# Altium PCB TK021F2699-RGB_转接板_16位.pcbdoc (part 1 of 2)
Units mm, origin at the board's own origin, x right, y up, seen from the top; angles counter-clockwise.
Board outline 79.4 x 75.01 mm, 2 copper layers (Top Layer, Bottom Layer), stack 1.58 mm thick; 9 components, 29 nets, 98 pads, 116 vias.
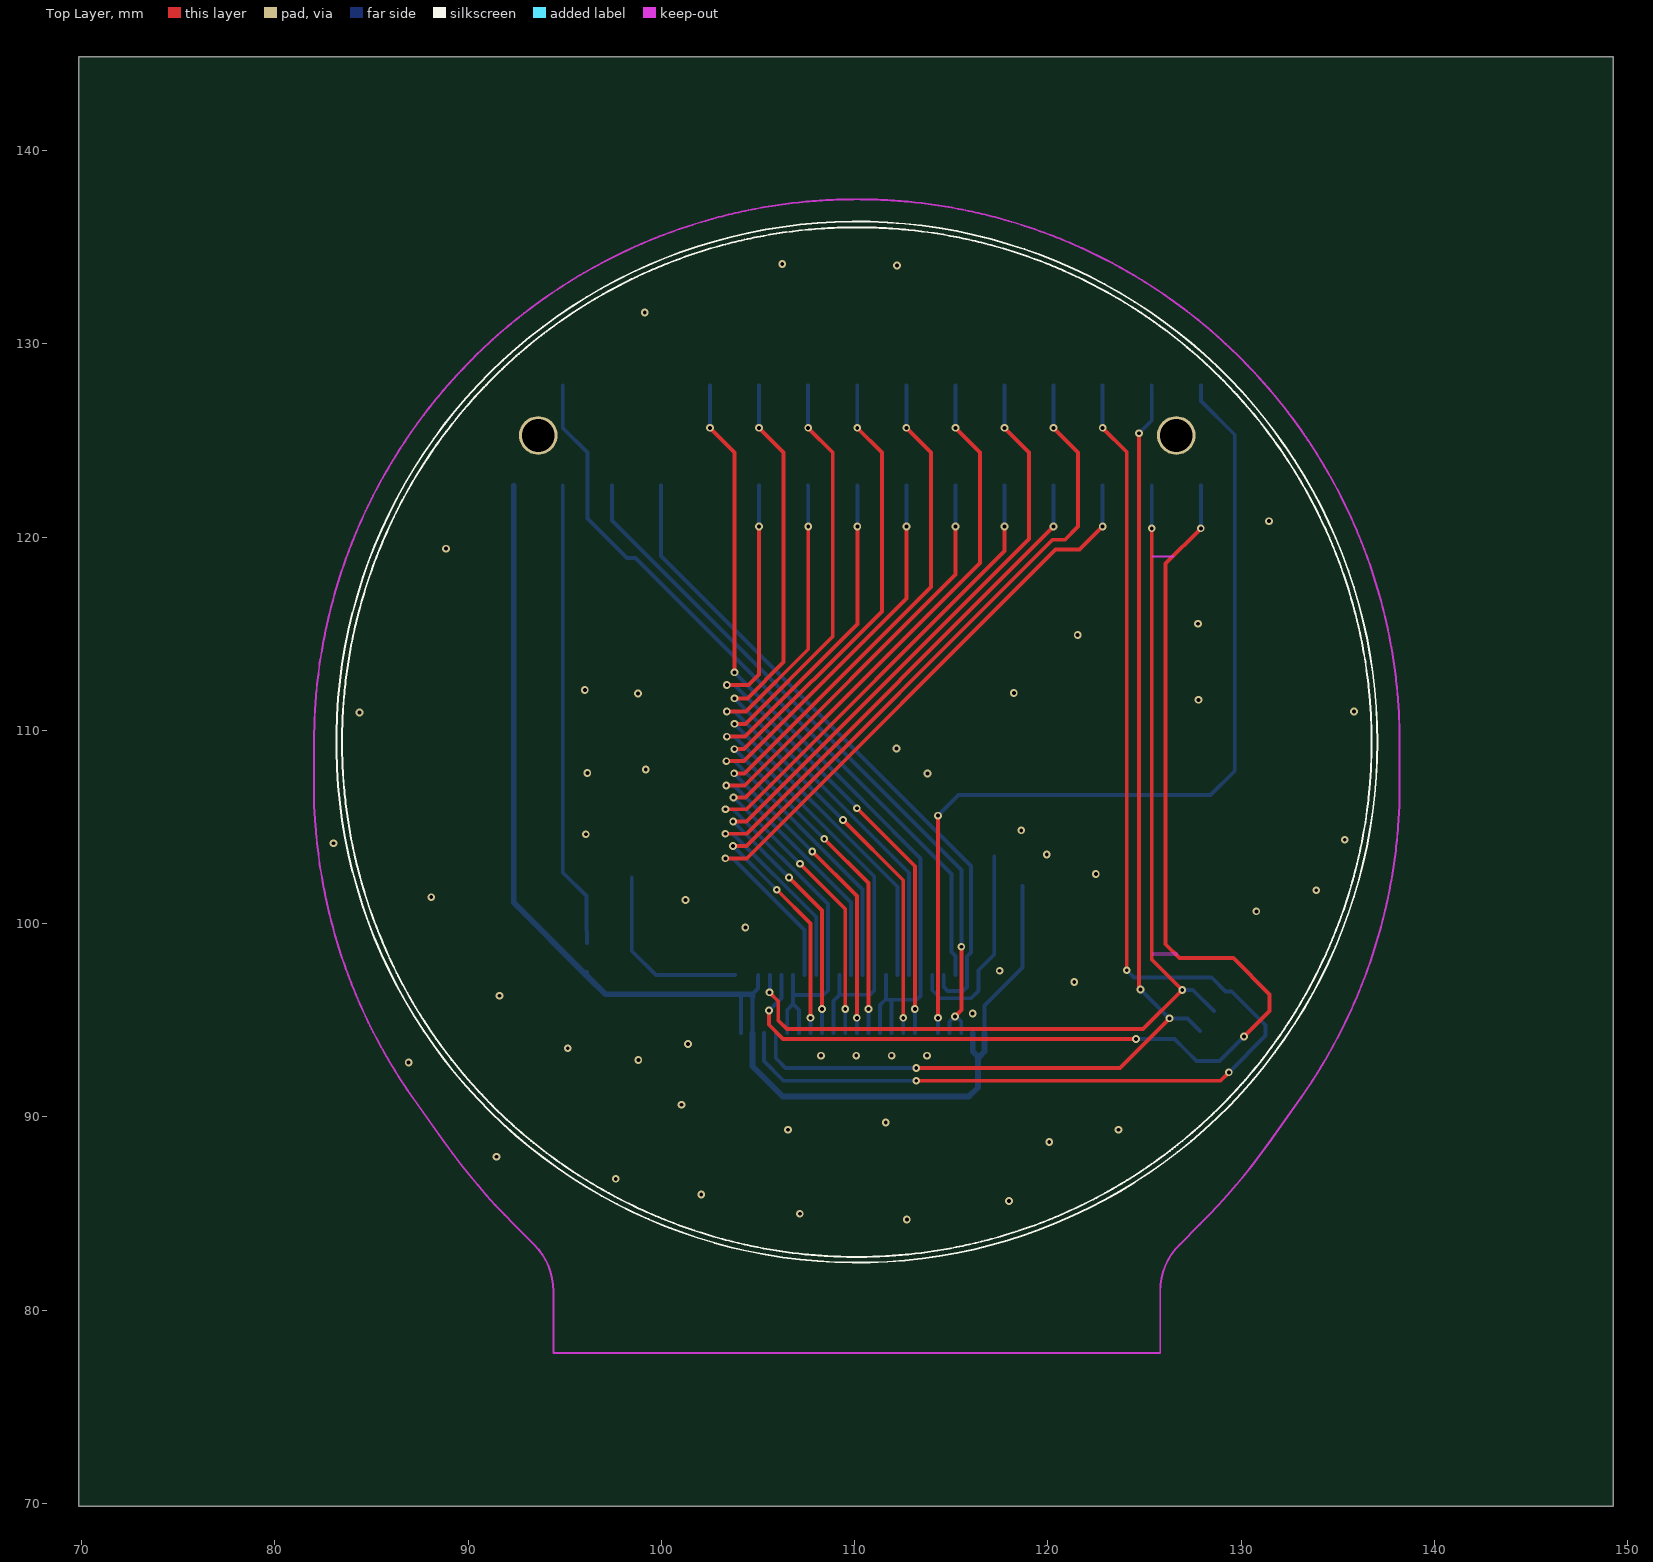
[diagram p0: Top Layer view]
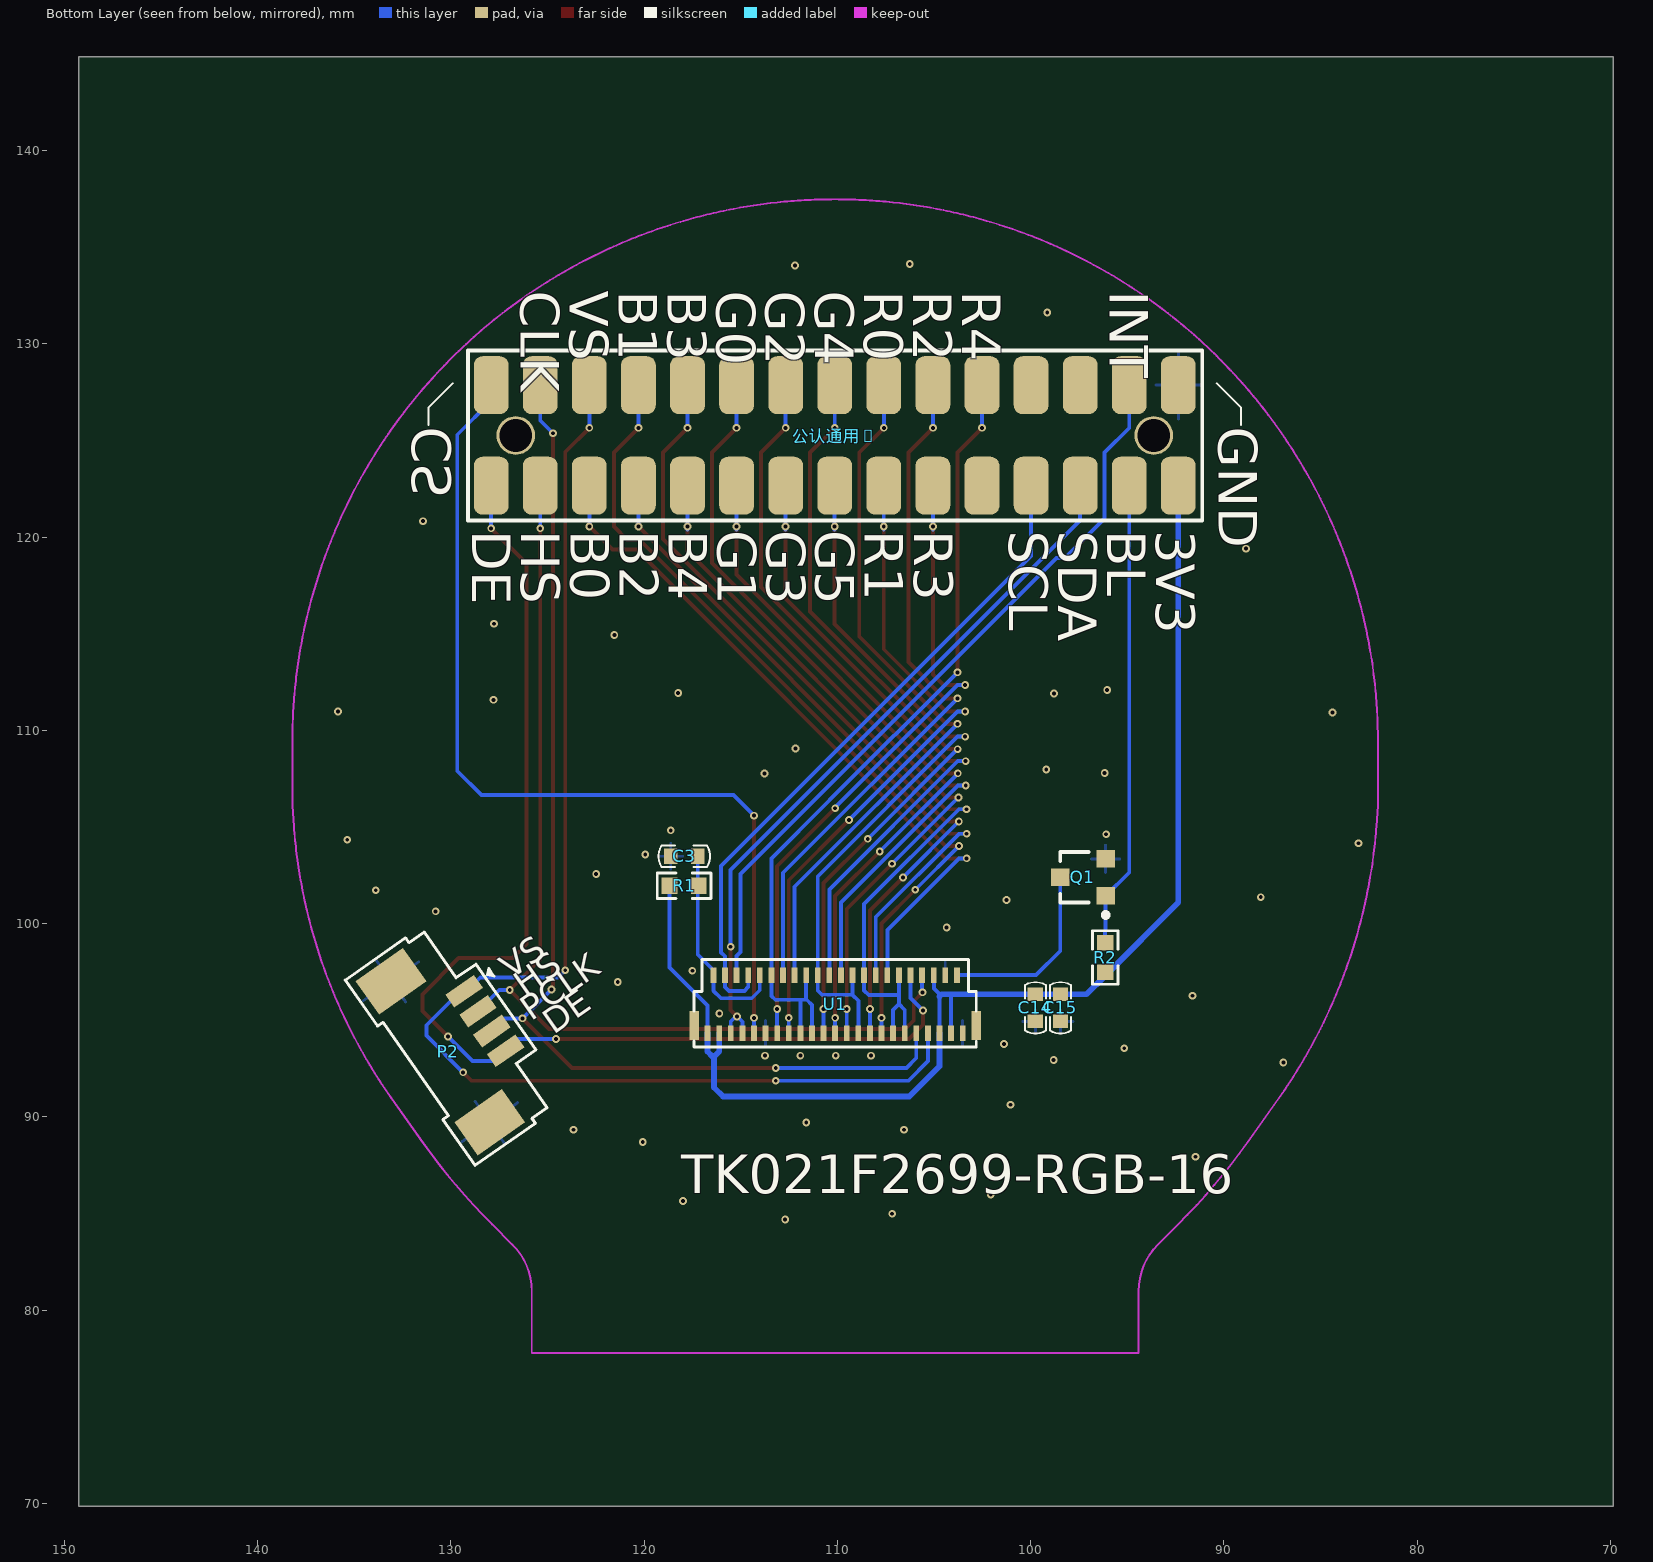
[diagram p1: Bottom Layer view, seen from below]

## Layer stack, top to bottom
Top Solder Mask Layer: solder mask 0.01, Dk 3.3
Top Layer: signal copper 0.035
Dielectric1: surface 1.51, FR4, Dk 4.5
Bottom Layer: signal copper 0.035
Bottom Solder Mask Layer: solder mask 0.01, Dk 3.3

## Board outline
149.25,69.85 69.85,69.85 69.85,144.856 149.25,144.856

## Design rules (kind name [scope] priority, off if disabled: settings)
BoardOutlineClearance Clearance [All] p0: genericclearance=0.254 ignorepadtopadclearanceinfootprint=FALSE except(0: Arc-SplitContinuation Track-SplitContinuation SMDPad-SplitContinuation THPad-SplitContinuation Via-SplitContinuation Fill-SplitContinuation Poly-SplitContinuation Region-SplitContinuation Text-SplitContinuation)
BoardOutlineClearance Clearance_Polygon [All] p0: genericclearance=0.254 ignorepadtopadclearanceinfootprint=FALSE except(0: Arc-SplitContinuation Track-SplitContinuation SMDPad-SplitContinuation THPad-SplitContinuation Via-SplitContinuation Fill-SplitContinuation Poly-SplitContinuation Region-SplitContinuation Text-SplitContinuation)
BoardOutlineClearance Plane_PlaneConnect [All] p0: genericclearance=0.254 ignorepadtopadclearanceinfootprint=FALSE except(0: Arc-SplitContinuation Track-SplitContinuation SMDPad-SplitContinuation THPad-SplitContinuation Via-SplitContinuation Fill-SplitContinuation Poly-SplitContinuation Region-SplitContinuation Text-SplitContinuation)
BoardOutlineClearance Copper_PolygonConnect [All] p0: genericclearance=0.254 ignorepadtopadclearanceinfootprint=FALSE except(0: Arc-SplitContinuation Track-SplitContinuation SMDPad-SplitContinuation THPad-SplitContinuation Via-SplitContinuation Fill-SplitContinuation Poly-SplitContinuation Region-SplitContinuation Text-SplitContinuation)
BoardOutlineClearance Copper_PolygonConnect_1 [All] p0: genericclearance=0.254 ignorepadtopadclearanceinfootprint=FALSE except(0: Arc-SplitContinuation Track-SplitContinuation SMDPad-SplitContinuation THPad-SplitContinuation Via-SplitContinuation Fill-SplitContinuation Poly-SplitContinuation Region-SplitContinuation Text-SplitContinuation)
BoardOutlineClearance otherClearance [All] p0: genericclearance=0.254 ignorepadtopadclearanceinfootprint=FALSE except(0: Arc-SplitContinuation Track-SplitContinuation SMDPad-SplitContinuation THPad-SplitContinuation Via-SplitContinuation Fill-SplitContinuation Poly-SplitContinuation Region-SplitContinuation Text-SplitContinuation)
Clearance [All] p1: gap=0.178 ignorepadtopadclearanceinfootprint=FALSE
Clearance Clearance_Polygon [All] p1: gap=0.178 ignorepadtopadclearanceinfootprint=FALSE
Clearance Plane_PlaneConnect [All] p1: gap=0.178 ignorepadtopadclearanceinfootprint=FALSE
Clearance Copper_PolygonConnect [All] p1: gap=0.178 ignorepadtopadclearanceinfootprint=FALSE
Clearance Copper_PolygonConnect_1 [All] p1: gap=0.178 ignorepadtopadclearanceinfootprint=FALSE
Clearance otherClearance [All] p1: gap=0.178 ignorepadtopadclearanceinfootprint=FALSE
DiffPairsRouting [All] p1: maxuncoupledlength=500 minlimit=5.9055 maxlimit=Infinity mostfreqgap=7.874 toplayer_minwidth=7.874 toplayer_prefwidth=7.874 toplayer_maxwidth=7.874 bottomlayer_minwidth=7.874 bottomlayer_prefwidth=7.874 bottomlayer_maxwidth=7.874
PolygonConnect [All] p1: connectstyle=Relief reliefentries=4 reliefconductorwidth=5.9055 polygonreliefangle="90 Angle" airgapwidth=10
PolygonConnect PolygonConnect_1 [All] p1: connectstyle=Direct reliefentries=4 reliefconductorwidth=10 polygonreliefangle="90 Angle" airgapwidth=10
RoutingVias [All] p1: viastyle="Through Hole" holewidth=7.874 minholewidth=7.874 maxholewidth=27.9922 width=7.874 minwidth=7.874 maxwidth=27.9922
SolderMaskExpansion [All] p1: useseparateexpansions=TRUE expansion=3.937 expansionbottom=3.937
Width [All] p1: maxlimit=16 minlimit=8 preferedwidth=8
2 further rules are at their usual default settings.

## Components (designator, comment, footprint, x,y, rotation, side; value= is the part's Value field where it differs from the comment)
C3 "" C0603 117.932,103.48 r0 bottom
C14 "" C0603-1 99.746,96.345 r270 bottom
C15 "" C0603-2 98.45,96.345 r270 bottom
P2 "" BHEADSMD1x4 129.311,96.495 r55 bottom locked
Q1 "" SOT23A 96.114,101.448 r90 bottom
R1 "" R0603 117.932,101.956 r0 bottom
R2 "" R0603 96.139,98.247 r270 bottom
U1 "" TK-45P 103.512,94.336 r0 bottom locked
公认通用1 "" P_Head_2x15 127.912,127.864 r180 bottom locked

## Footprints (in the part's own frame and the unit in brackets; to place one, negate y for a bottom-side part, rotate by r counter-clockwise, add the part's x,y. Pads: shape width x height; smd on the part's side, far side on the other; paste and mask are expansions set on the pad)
BHEADSMD1x4 [mil]
  rect 32x71 smd: 1(0,0) 2(-49.21,0) 3(-98.43,0) 4(-147.64,0)
  rect 83x118 smd: 5(102.36,110.24) 6(-248.03,110.24)
  silkscreen extent -303,-68 158,185
C0603 [mm]
  rect 0.7x0.8 smd: 1(-0.712,-0.007) 2(0.688,-0.007)
  silkscreen extent -1.33,-0.56 1.31,0.54
C0603-1 [mm]
  rect 0.7x0.8 smd: 1(0,0) 2(1.4,0)
  silkscreen extent -0.62,-0.55 2.02,0.55
C0603-2 [mm]
  rect 0.7x0.8 smd: 1(0,0) 2(1.4,0)
  silkscreen extent -0.62,-0.55 2.02,0.55
P_Head_2x15 [mm]
  round 2 hole 1.7: 0(1.27,-2.6) 0(34.29,-2.6)
  rrect50% 1.8x3 smd: 1(0,0) 2(0,-5.2) 3(2.54,0) 4(2.54,-5.2) 5(5.08,0) 6(5.08,-5.2) 7(7.62,0) 8(7.62,-5.2) 9(10.16,0) 10(10.16,-5.2) 11(12.7,0) 12(12.7,-5.2) 13(15.24,0) 14(15.24,-5.2) 15(17.78,0) 16(17.78,-5.2) 17(20.32,0) 18(20.32,-5.2) 19(22.86,0) 20(22.86,-5.2) 21(25.4,0) 22(25.4,-5.2) 23(27.94,0) 24(27.94,-5.2) 25(30.48,0) 26(30.48,-5.2) 27(33.02,0) 28(33.02,-5.2) 29(35.56,0) 30(35.56,-5.2)
  silkscreen extent -1.2,-7 36.8,1.8
R0603 [mm]
  rect 0.806x0.864 smd: 1(-0.753,0) 2(0.753,0)
  silkscreen extent -1.39,-0.66 1.39,0.66
SOT23A [mm]
  rect 0.9x0.95 smd: 1(0,0) 2(1.9,0) 3(0.95,2.35)
  silkscreen extent -1.12,-0.12 2.25,2.35
TK-45P [mm]
  rect 0.5x1.5 smd: 0(-0.7,-0.4) 0(13.9,-0.4)
  rect 0.3x0.8 smd: 1(0,0) 2(0.3,-3) 3(0.6,0) 4(0.9,-3) 5(1.2,0) 6(1.5,-3) 7(1.8,0) 8(2.1,-3) 9(2.4,0) 10(2.7,-3) 11(3,0) 12(3.3,-3) 13(3.6,0) 14(3.9,-3) 15(4.2,0) 16(4.5,-3) 17(4.8,0) 18(5.1,-3) 19(5.4,0) 20(5.7,-3) 21(6,0) 22(6.3,-3) 23(6.6,0) 24(6.9,-3) 25(7.2,0) 26(7.5,-3) 27(7.8,0) 28(8.1,-3) 29(8.4,0) 30(8.7,-3) 31(9,0) 32(9.3,-3) 33(9.6,0) 34(9.9,-3) 35(10.2,0) 36(10.5,-3) 37(10.8,0) 38(11.1,-3) 39(11.4,0) 40(11.7,-3) 41(12,0) 42(12.3,-3) 43(12.6,0) 44(12.9,-3) 45(13.2,0)
  silkscreen extent -0.7,-3.8 13.9,0.73

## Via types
v1: diameter 0.4, hole 0.2, Top Layer to Bottom Layer, 116 vias

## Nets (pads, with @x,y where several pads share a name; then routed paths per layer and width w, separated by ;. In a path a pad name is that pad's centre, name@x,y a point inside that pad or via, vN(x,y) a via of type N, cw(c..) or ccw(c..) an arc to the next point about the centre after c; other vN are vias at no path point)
3.3V: C14.1 C15.1 R1.2 R2.2 U1.3 U1.5 U1.6 U1.43 U1.45 公认通用1.30 | length 68.2
  Bottom Layer w0.2: R2.2@96.139,97.307 R2.2@96.139,97.494 ; U1.3@104.112,94.336 104.112,96.33 104.127,96.345 ; U1.5@104.712,94.336 104.712,96.228 104.712,96.355 105.004,96.647 105.004,97.328 U1.6@105.012,97.336 ; U1.45@116.712,94.336 116.712,95.757 118.686,97.731 R1.2@118.686,101.956
  Bottom Layer w0.3: 公认通用1.30@92.352,122.664 92.352,101.095 96.139,97.307 97.101,96.345 C15.1@98.45,96.345 C14.1@99.746,96.345 104.127,96.345 104.595,96.345 104.712,96.228 ; U1.5@104.712,94.336 104.712,92.617 106.279,91.05 115.909,91.05 116.383,91.524 116.383,93.116 116.112,93.387 U1.43@116.112,94.336 ; 116.441,93.116 116.712,93.387 U1.45@116.712,94.336
B0: U1.14 公认通用1.6 | length 36.7
  Top Layer w0.2: v1(103.308,103.378) 104.417,103.378 120.393,119.355 121.64,119.355 v1(122.832,120.546)
  Bottom Layer w0.2: v1(103.308,103.378) 103.708,103.378 107.412,99.674 U1.14@107.412,97.336 ; v1(122.832,120.546) 公认通用1.6@122.832,122.664
B1: U1.15 公认通用1.7 | length 43.9
  Top Layer w0.2: v1(103.708,104.014) 104.395,104.014 120.244,119.863 120.879,119.863 121.564,120.548 121.564,124.384 v1(120.292,125.656) ; v1(105.969,101.754) 107.712,100.011 v1(107.712,95.123)
  Bottom Layer w0.2: v1(103.708,104.014) v1(105.969,101.754) ; U1.15@107.712,94.336 v1(107.712,95.123) ; v1(120.292,125.656) 公认通用1.7@120.292,127.864
B2: U1.16 公认通用1.8 | length 35.2
  Top Layer w0.2: v1(103.308,104.648) 104.394,104.648 v1(120.292,120.546)
  Bottom Layer w0.2: v1(103.308,104.648) 103.711,104.648 108.012,100.347 U1.16@108.012,97.336 ; v1(120.292,120.546) 公认通用1.8@120.292,122.664
B3: U1.17 公认通用1.9 | length 42.7
  Top Layer w0.2: v1(103.709,105.282) 104.393,105.282 119.024,119.913 119.024,124.384 v1(117.752,125.656) ; v1(106.606,102.389) 108.312,100.684 v1(108.312,95.581)
  Bottom Layer w0.2: v1(103.709,105.282) 103.713,105.282 v1(106.606,102.389) ; U1.17@108.312,94.336 v1(108.312,95.581) ; v1(117.752,125.656) 公认通用1.9@117.752,127.864
B4: U1.11 U1.12 U1.13 U1.18 公认通用1.10 | length 41.8
  Top Layer w0.2: v1(103.311,105.921) 104.397,105.921 117.757,119.281 v1@117.757,120.396
  Bottom Layer w0.2: v1(103.311,105.921) 103.711,105.921 108.612,101.02 U1.18@108.612,97.336 108.612,96.547 108.376,96.311 106.833,96.311 106.812,96.332 ; U1.11@106.512,94.336 106.512,95.539 106.812,95.839 ; U1.12@106.812,97.336 106.812,96.332 ; U1.13@107.112,94.336 107.112,95.539 106.812,95.839 ; 公认通用1.10@117.752,122.664 117.757,122.659 v1@117.757,120.396 ; 106.812,95.839 106.812,96.332
  other v1: 117.757,120.546
BL_CTR: Q1.1 R2.1 公认通用1.28 | length 24.2
  Bottom Layer w0.2: 公认通用1.28@94.892,122.664 94.892,102.644 96.089,101.448 Q1.1@96.114,101.448 96.114,99.629 96.139,99.604 R2.1@96.139,99.001
CS: U1.37 公认通用1.1 | length 48.3
  Top Layer w0.2: v1(114.312,95.123) v1(114.312,105.588)
  Bottom Layer w0.2: U1.37@114.312,94.336 v1(114.312,95.123) ; v1(114.312,105.588) 115.379,106.655 128.422,106.655 129.667,107.899 129.667,125.298 127.912,127.053 公认通用1.1@127.912,127.864
G0: U1.21 公认通用1.11 | length 42.1
  Top Layer w0.2: v1(103.734,106.529) 104.345,106.529 116.484,118.669 116.484,124.384 v1(115.212,125.656) ; v1(107.166,103.102) 109.512,100.756 v1(109.512,95.581)
  Bottom Layer w0.2: v1(103.734,106.529) 103.739,106.529 v1(107.166,103.102) ; U1.21@109.512,94.336 v1(109.512,95.581) ; v1(115.212,125.656) 公认通用1.11@115.212,127.864
G1: U1.22 公认通用1.12 | length 33.7
  Top Layer w0.2: v1(103.35,107.154) 104.309,107.154 115.217,118.062 v1@115.217,120.396
  Bottom Layer w0.2: v1(103.35,107.154) 103.75,107.154 109.812,101.093 U1.22@109.812,97.336 ; 公认通用1.12@115.212,122.664 115.217,122.659 v1@115.217,120.396
  other v1: 115.217,120.546
G2: U1.23 公认通用1.13 | length 41.2
  Top Layer w0.2: v1(103.763,107.778) 104.298,107.778 113.944,117.424 113.944,124.384 v1(112.672,125.656) ; v1(107.802,103.738) 110.112,101.429 v1(110.112,95.123)
  Bottom Layer w0.2: v1(103.763,107.778) v1(107.802,103.738) ; U1.23@110.112,94.336 v1(110.112,95.123) ; v1(112.672,125.656) 公认通用1.13@112.672,127.864
G3: U1.24 公认通用1.14 | length 32.9
  Top Layer w0.2: v1(103.359,108.407) 104.267,108.407 112.677,116.817 v1@112.677,120.396
  Bottom Layer w0.2: v1(103.359,108.407) 103.77,108.407 110.412,101.766 U1.24@110.412,97.336 ; 公认通用1.14@112.672,122.664 112.677,122.659 v1@112.677,120.396
  other v1: 112.677,120.546
G4: U1.25 公认通用1.15 | length 40.4
  Top Layer w0.2: v1(103.772,109.029) 104.28,109.029 111.404,116.154 111.404,124.384 v1(110.132,125.656) ; v1(108.426,104.388) 110.712,102.102 v1(110.712,95.581)
  Bottom Layer w0.2: v1(103.772,109.029) 103.784,109.029 v1(108.426,104.388) ; v1(110.132,125.656) 公认通用1.15@110.132,127.864 ; U1.25@110.712,94.336 v1(110.712,95.581)
G5: U1.19 U1.20 U1.26 公认通用1.16 | length 37.9
  Top Layer w0.2: v1(103.384,109.677) 104.318,109.677 110.137,115.496 v1@110.137,120.396
  Bottom Layer w0.2: v1(103.384,109.677) 103.773,109.677 111.012,102.438 U1.26@111.012,97.336 111.012,96.534 110.795,96.317 109.22,96.317 109.212,96.309 ; U1.19@108.912,94.336 108.912,96.009 109.212,96.309 ; U1.20@109.212,97.336 109.212,96.309 ; 公认通用1.16@110.132,122.664 110.137,122.659 v1@110.137,120.396
  other v1: 110.137,120.546
GND: C3.2 C14.2 C15.2 P2.5 P2.6 Q1.2 U1.1 U1.4 U1.35 公认通用1.29
  other v1: 112.7,84.684 107.163,84.988 117.983,85.649 102.057,85.979 97.638,86.792 91.465,87.935 120.066,88.697 106.553,89.332 123.647,89.332 111.608,89.713 101.041,90.627 86.919,92.812 98.806,92.939 108.255,93.167 110.084,93.167 111.912,93.167 113.741,93.167 95.148,93.548 101.371,93.777 116.103,95.352 91.618,96.266 121.361,96.977 117.5,97.561 104.343,99.797 130.785,100.635 101.244,101.219 88.087,101.371 133.883,101.727 122.479,102.565 119.939,103.581 83.033,104.159 135.357,104.343 96.088,104.623 118.618,104.826 113.767,107.772 96.164,107.798 99.187,107.975 112.166,109.068 84.379,110.922 135.839,110.973 127.787,111.582 98.781,111.912 118.237,111.938 96.037,112.09 121.539,114.935 127.762,115.519 88.849,119.405 131.445,120.828 99.136,131.623 112.192,134.061 106.248,134.137
INT: U1.40 公认通用1.27 | length 39.2
  Bottom Layer w0.2: 公认通用1.27@94.892,127.864 94.892,125.656 96.164,124.384 96.164,120.974 98.216,118.923 98.654,118.923 115.012,102.565 115.012,98.526 115.212,98.326 U1.40@115.212,97.336
LED-: Q1.3 U1.2 | length 9.7
  Bottom Layer w0.2: Q1.3@98.464,102.398 98.464,98.59 99.717,97.336 U1.2@103.812,97.336
R0: U1.30 公认通用1.17 | length 37
  Top Layer w0.2: v1(103.784,110.338) 104.343,110.338 108.864,114.859 108.864,124.384 v1(107.592,125.656)
  Bottom Layer w0.2: v1@103.786,110.338 112.212,101.912 U1.30@112.212,97.336 ; v1(107.592,125.656) 公认通用1.17@107.592,127.864
R1: U1.31 公认通用1.18 | length 34.7
  Top Layer w0.2: v1(103.384,110.974) 104.37,110.974 107.597,114.201 v1@107.597,120.396 ; v1(109.395,105.364) 112.512,102.248 v1(112.512,95.123)
  Bottom Layer w0.2: v1(103.384,110.974) 103.786,110.974 v1(109.395,105.364) ; 公认通用1.18@107.592,122.664 107.597,122.659 v1@107.597,120.396 ; U1.31@112.512,94.336 v1(112.512,95.123)
  other v1: 107.597,120.546
R2: U1.32 公认通用1.19 | length 36.2
  Top Layer w0.2: v1(103.784,111.658) 104.445,111.658 106.324,113.538 106.324,124.384 v1(105.052,125.656)
  Bottom Layer w0.2: v1(103.784,111.658) 103.787,111.658 112.812,102.634 U1.32@112.812,97.336 ; v1(105.052,125.656) 公认通用1.19@105.052,127.864
R3: U1.33 公认通用1.20 | length 33.9
  Top Layer w0.2: v1(103.384,112.344) 104.496,112.344 105.052,112.9 v1@105.052,120.396 ; v1(110.111,105.971) 113.112,102.97 v1(113.112,95.581)
  Bottom Layer w0.2: v1(103.384,112.344) 103.784,112.344 110.111,106.018 v1(110.111,105.971) ; v1@105.052,120.396 公认通用1.20@105.052,122.664 ; U1.33@113.112,94.336 v1(113.112,95.581)
  other v1: 105.052,120.546
R4: U1.27 U1.28 U1.29 U1.34 公认通用1.21 | length 42.9
  Top Layer w0.2: v1(102.512,125.656) 103.784,124.384 v1(103.784,113.005)
  Bottom Layer w0.2: v1(102.512,125.656) 公认通用1.21@102.512,127.864 ; v1(103.784,113.005) 110.269,106.52 ; 110.27,106.52 110.534,106.257 ; 110.534,106.255 113.412,103.377 U1.34@113.412,97.336 113.412,96.264 113.212,96.064 111.912,96.064 ; U1.27@111.312,94.336 111.312,95.792 111.583,96.064 ; U1.28@111.612,97.336 111.612,96.092 111.583,96.064 ; U1.29@111.912,94.336 111.912,96.064 ; 111.583,96.064 111.912,96.064
RST: C3.1 R1.1 U1.36 U1.44 | length 10.8
  Bottom Layer w0.2: U1.36@114.012,97.336 114.012,96.554 114.427,96.139 116.027,96.139 116.412,96.524 U1.44@116.412,97.336 116.412,97.586 117.22,98.394 C3.1@117.22,103.487
SCL: U1.38 U1.42 公认通用1.24 | length 34.7
  Bottom Layer w0.2: 公认通用1.24@99.972,122.664 99.972,119.019 116.012,102.979 116.012,98.511 115.812,98.311 U1.42@115.812,97.336 115.812,96.72 115.612,96.52 114.812,96.52 114.612,96.72 U1.38@114.612,97.336
SDA: U1.39 U1.41 公认通用1.26 | length 37.1
  Top Layer w0.2: v1(115.191,95.199) 115.519,95.527 v1(115.519,98.806)
  Bottom Layer w0.2: 公认通用1.26@97.432,122.664 97.432,120.862 115.519,102.775 v1(115.519,98.806) ; U1.39@114.912,94.336 114.912,94.92 v1(115.191,95.199) 115.24,95.199 115.512,94.927 U1.41@115.512,94.336
T_DE: P2.4 U1.10 公认通用1.2 | length 62.4
  Top Layer w0.2: v1(105.562,95.504) 105.562,94.767 106.299,94.031 v1(124.562,94.031) ; v1(127.912,120.456) 126.086,118.63 126.086,98.933 126.799,98.219 129.593,98.219 131.47,96.342 131.47,95.479 v1(130.145,94.154)
  Bottom Layer w0.2: v1(105.562,95.504) 106.212,96.153 U1.10@106.212,97.336 ; v1(124.562,94.031) 126.552,94.031 P2.4@127.16,93.423 127.695,92.888 128.88,92.888 v1(130.145,94.154) ; v1(127.912,120.456) 公认通用1.2@127.912,122.664
T_HSYNC: P2.2 U1.8 公认通用1.4 | length 53.3
  Top Layer w0.2: v1(105.588,96.444) 106.045,95.987 106.045,94.996 106.502,94.539 124.917,94.539 v1(126.949,96.571) 125.372,98.148 v1(125.372,120.456)
  Bottom Layer w0.2: v1(105.588,96.444) 105.612,96.468 U1.8@105.612,97.336 ; v1(125.372,120.456) 公认通用1.4@125.372,122.664 ; v1(126.949,96.571) 127.494,96.571 P2.2@128.594,95.471
T_PCLK: P2.3 U1.9 公认通用1.3 | length 58.5
  Top Layer w0.2: v1(113.182,92.532) 123.723,92.532 v1(126.289,95.098) ; v1(124.714,125.374) 124.714,96.672 v1(124.79,96.596)
  Bottom Layer w0.2: U1.9@105.912,94.336 105.912,93.046 106.426,92.532 v1(113.182,92.532) ; v1(124.714,125.374) 125.372,126.032 公认通用1.3@125.372,127.864 ; v1(124.79,96.596) v1(126.289,95.098) 127.227,95.098 P2.3@127.877,94.447
T_VSYNC: P2.1 U1.7 公认通用1.5 | length 68.5
  Top Layer w0.2: v1(113.182,91.872) 128.93,91.872 v1(129.362,92.304) ; v1(122.832,125.656) 124.079,124.409 v1(124.079,97.587)
  Bottom Layer w0.2: U1.7@105.312,94.336 105.312,92.884 106.324,91.872 v1(113.182,91.872) ; v1(122.832,125.656) 公认通用1.5@122.832,127.864 ; v1(124.079,97.587) 124.46,97.206 128.479,97.206 129.19,96.495 P2.1@129.311,96.495 129.515,96.495 131.267,94.742 131.267,94.209 v1(129.362,92.304)
pads on no net: U1.0 公认通用1.0 公认通用1.22 公认通用1.23 公认通用1.25

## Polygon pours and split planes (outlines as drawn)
GND on Bottom Layer (solid, remove dead copper, pour order 2): 76.2,138.506 142.9,138.506 142.9,76.479 76.2,76.479
GND on Top Layer (solid, remove dead copper, pour order 0): 81.686,138.227 138.76,138.227 138.76,76.2 81.686,76.2

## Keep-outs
Top Layer:
  region: 125.448,98.501 126.67,98.501 126.67,98.374 125.448,98.374
  region: 125.424,119.05 126.493,119.05 126.493,118.971 125.424,118.971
